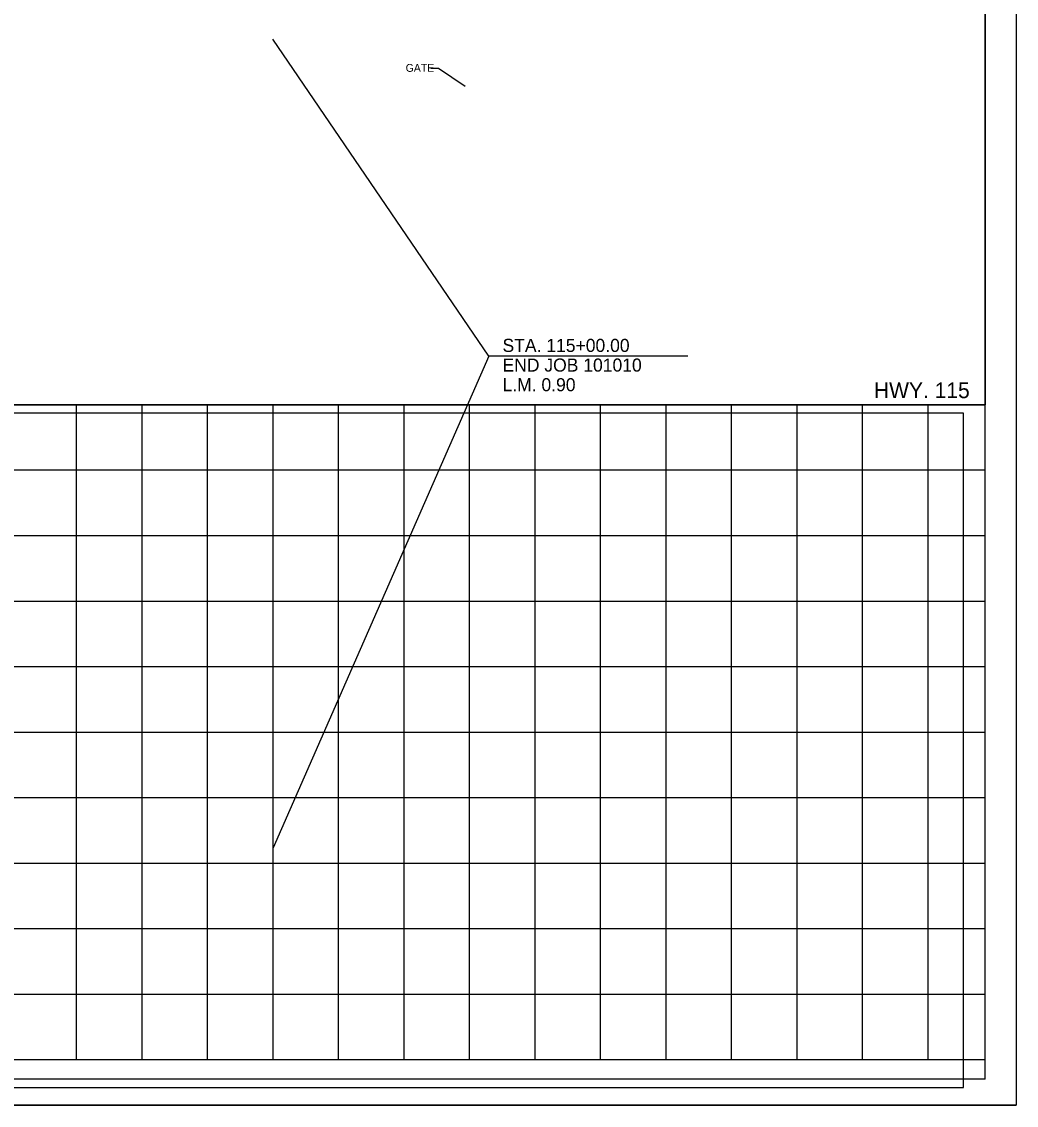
# Model space of a CAD drawing. Extents: x 9709 to 12772, y 9986 to 11806.
# Drawn here: x 10855 to 11615, y 9986 to 10813 of the extents above; entities that cross this region are included whole.
import ezdxf

# ---------------------------------------------------------------- set-up
doc = ezdxf.new("R2010")
doc.units = 0
for name, color, linetype in [('GREEN_TXT', 7, 'Continuous'), ('JOB Text', 7, 'Continuous'), ('R_No Plot', 7, 'Continuous'), ('SEAL-INFO', 7, 'Continuous'), ('TEXT', 7, 'Continuous')]:
    doc.layers.add(name, color=color, linetype=linetype)

msp = doc.modelspace()

# ---------------------------------------------------------------- linework, layer by layer
at = {"layer": 'GREEN_TXT'}
for p, q in [((11591.06, 10006.32), (11591.06, 11033.62)), ((11591.06, 10521.02), (10010.16, 10521.02)), ((10897.46, 10021.02), (10897.46, 10521.02)), ((10947.46, 10021.02), (10947.46, 10521.02)), ((10997.46, 10021.02), (10997.46, 10521.02)), ((11047.46, 10021.02), (11047.46, 10521.02)), ((11097.46, 10021.02), (11097.46, 10521.02)), ((11147.46, 10021.02), (11147.46, 10521.02)), ((11197.46, 10021.02), (11197.46, 10521.02)), ((11247.46, 10021.02), (11247.46, 10521.02)), ((11297.46, 10021.02), (11297.46, 10521.02)), ((11347.46, 10021.02), (11347.46, 10521.02)), ((11397.46, 10021.02), (11397.46, 10521.02)), ((11447.46, 10021.02), (11447.46, 10521.02)), ((11497.46, 10021.02), (11497.46, 10521.02)), ((11547.46, 10021.02), (11547.46, 10521.02)), ((11591.06, 10471.02), (10010.16, 10471.02)), ((11591.06, 10421.02), (10010.16, 10421.02)), ((11591.06, 10371.02), (10010.16, 10371.02)), ((11591.06, 10321.02), (10010.16, 10321.02)), ((11591.06, 10271.02), (10010.16, 10271.02)), ((11591.06, 10221.02), (10010.16, 10221.02)), ((11591.06, 10171.02), (10010.16, 10171.02)), ((11591.06, 10121.02), (10010.16, 10121.02)), ((11591.06, 10071.02), (10010.16, 10071.02)), ((11591.06, 10021.02), (10010.16, 10021.02)), ((11591.06, 10006.32), (10010.16, 10006.32))]:
    msp.add_line(p, q, dxfattribs=at)
at = {"layer": 'JOB Text'}
msp.add_line((11212.23, 10558.21), (11047.46, 10183.02), dxfattribs=at)
msp.add_lwpolyline([(11364.17, 10558.21), (11212.23, 10558.21), (11047.22, 10800.05)], dxfattribs=at)
at = {"layer": 'R_No Plot'}
msp.add_line((9948.15, 9986.43), (11614.82, 9986.43), dxfattribs=at)
for points in [[(9948.15, 11053.12), (11614.85, 11053.12), (11614.85, 9986.43), (9948.15, 9986.43)], [(11179.76, 11033.62), (11179.76, 10984.22), (11358.42, 10984.22), (11358.42, 10969.62), (11477.57, 10969.62), (11477.57, 10851.23), (11591.06, 10851.23), (11591.06, 10521.02), (10010.16, 10521.02), (10010.16, 11033.62)]]:
    msp.add_lwpolyline(points, close=True, dxfattribs=at)
at = {"layer": 'SEAL-INFO'}
for points in [[(11326.26, 10984.22), (11179.76, 10984.22), (11179.76, 11033.62), (10010.16, 11033.62), (10010.16, 10521.02), (11297.46, 10521.02), (11591.06, 10521.02), (11591.06, 10556.02), (11591.06, 10556.02), (11591.06, 10969.62), (11326.26, 10969.62)], [(10000, 10000), (11574.6, 10000), (11574.6, 10514.7), (10000, 10514.7)]]:
    msp.add_lwpolyline(points, close=True, dxfattribs=at)
at = {"layer": 'TEXT'}
msp.add_lwpolyline([(11167.95, 10777.97), (11173.6, 10777.97), (11194.03, 10764.26)], dxfattribs=at)

# ---------------------------------------------------------------- texts
msp.add_text('HWY. 115', height=12).set_placement((11506.15, 10526.1))
at = {"layer": 'JOB Text'}
for s, p in [('STA. 115+00.00', (11222.58, 10561.34)), ('END JOB 101010', (11222.58, 10546.34)), ('L.M. 0.90', (11222.58, 10531.34))]:
    msp.add_text(s, height=10, dxfattribs=at).set_placement(p)
at = {"layer": 'TEXT'}
msp.add_text('GATE', height=6, dxfattribs=at).set_placement((11148.62, 10775.11))

doc.saveas('drawing.dxf')
